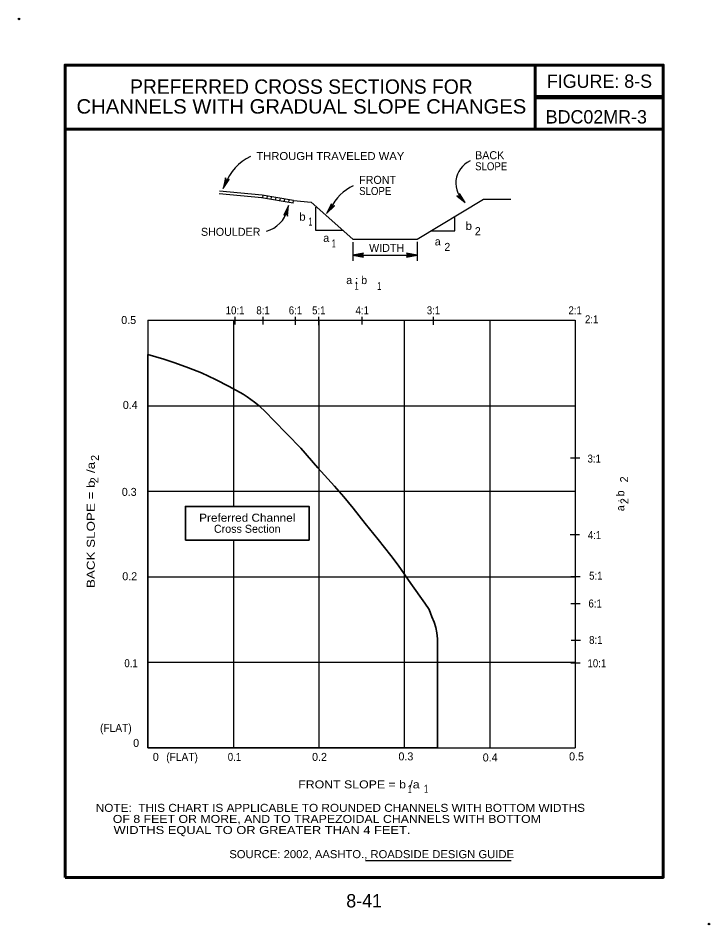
# Model space of a CAD drawing. Extents: x 12.266 to 12.941, y 5.964 to 6.848.
import ezdxf
from ezdxf.enums import TextEntityAlignment as Align

# ---------------------------------------------------------------- set-up
doc = ezdxf.new("R2010")
doc.units = 0
doc.header["$LTSCALE"] = 0.0031
doc.header["$PDMODE"] = 32
doc.header["$PDSIZE"] = 0.00155
doc.layers.add('1', color=7, linetype='Continuous', lineweight=25)
doc.layers.add('24', color=7, linetype='Continuous', lineweight=25)

msp = doc.modelspace()

# ---------------------------------------------------------------- linework, layer by layer
at = {"layer": '1', "lineweight": 60}
for p, q in [((12.769958, 6.73995), (12.769958, 6.802475)), ((12.895008, 6.771217), (12.769958, 6.771217)), ((12.895008, 6.771208), (12.769958, 6.771208)), ((12.895008, 6.73995), (12.311442, 6.73995))]:
    msp.add_line(p, q, dxfattribs=at)
at = {"layer": '1', "lineweight": 90}
msp.add_line((12.770025, 6.771233), (12.895008, 6.771233), dxfattribs=at)
at = {"layer": '1'}
for p, q in [((12.503358, 6.673242), (12.461833, 6.676883)), ((12.504283, 6.673117), (12.504742, 6.675692)), ((12.508517, 6.672367), (12.508975, 6.674942)), ((12.533908, 6.667842), (12.503133, 6.673275)), ((12.512542, 6.67165), (12.513, 6.674225)), ((12.516842, 6.670875), (12.5173, 6.67345)), ((12.521108, 6.670117), (12.521567, 6.672692)), ((12.525242, 6.669392), (12.5257, 6.671958)), ((12.529633, 6.668608), (12.530092, 6.671183)), ((12.533908, 6.667842), (12.534375, 6.670417)), ((12.534375, 6.670417), (12.5517, 6.668908)), ((12.592292, 6.632867), (12.5517, 6.668908)), ((12.654817, 6.632867), (12.719567, 6.671783)), ((12.719567, 6.671783), (12.746233, 6.671783)), ((12.556067, 6.64125), (12.556067, 6.664133)), ((12.691667, 6.640917), (12.691667, 6.654792)), ((12.582117, 6.64125), (12.556067, 6.64125)), ((12.668217, 6.640917), (12.691667, 6.640917)), ((12.592292, 6.632867), (12.654817, 6.632867)), ((12.592292, 6.6299), (12.592292, 6.611658)), ((12.654817, 6.630217), (12.654817, 6.611658)), ((12.592292, 6.617233), (12.654817, 6.617233)), ((12.392242, 6.553717), (12.392242, 6.136883)), ((12.475608, 6.553717), (12.475608, 6.37225)), ((12.4773, 6.549542), (12.4773, 6.557042)), ((12.504592, 6.549725), (12.504592, 6.557042)), ((12.536217, 6.549225), (12.536217, 6.557042)), ((12.558975, 6.548908), (12.558975, 6.557042)), ((12.558975, 6.553717), (12.558975, 6.136883)), ((12.601367, 6.549542), (12.601367, 6.557042)), ((12.642342, 6.553717), (12.642342, 6.136883)), ((12.670892, 6.549225), (12.670892, 6.557042)), ((12.725708, 6.553717), (12.725708, 6.136883)), ((12.392242, 6.47035), (12.809075, 6.47035)), ((12.804683, 6.419567), (12.813775, 6.419567)), ((12.392242, 6.386983), (12.809075, 6.386983)), ((12.475608, 6.339442), (12.475608, 6.136883)), ((12.804375, 6.344725), (12.813458, 6.344725)), ((12.392242, 6.303617), (12.809075, 6.303617)), ((12.805, 6.303875), (12.814083, 6.303875)), ((12.805, 6.27775), (12.814083, 6.27775)), ((12.805317, 6.241892), (12.8144, 6.241892)), ((12.392242, 6.22025), (12.809075, 6.22025)), ((12.805, 6.21975), (12.814083, 6.21975)), ((12.392242, 6.136883), (12.809075, 6.136883)), ((12.604633, 6.027142), (12.746742, 6.027142))]:
    msp.add_line(p, q, dxfattribs=at)
at = {"layer": '1', "lineweight": 60}
msp.add_lwpolyline([(12.311442, 6.010492), (12.895008, 6.010492), (12.895008, 6.802475), (12.311442, 6.802475)], close=True, dxfattribs=at)
at = {"layer": '1'}
for points in [[(12.534375, 6.670417), (12.503592, 6.67585), (12.462058, 6.679483)], [(12.392242, 6.553717), (12.809075, 6.553717), (12.809075, 6.136883)]]:
    msp.add_lwpolyline(points, dxfattribs=at)
at = {"layer": '1', "lineweight": 35}
for points in [[(12.67475, 6.136883), (12.392242, 6.136883), (12.392242, 6.520367), (12.407892, 6.515742), (12.418675, 6.51235), (12.431858, 6.507475), (12.444483, 6.502492), (12.458083, 6.495908), (12.4716, 6.48915), (12.48515, 6.481592), (12.489, 6.4792), (12.496258, 6.473808), (12.500725, 6.470208), (12.507225, 6.464208), (12.514708, 6.45625), (12.541375, 6.428908), (12.557983, 6.409867), (12.57435, 6.392008), (12.583442, 6.381567), (12.592625, 6.370475), (12.604267, 6.355458), (12.616842, 6.340042), (12.629108, 6.324375), (12.636367, 6.314967), (12.648883, 6.297033), (12.66235, 6.278025), (12.666592, 6.271617), (12.669358, 6.264442), (12.671517, 6.259358), (12.673275, 6.254067), (12.674208, 6.248967), (12.67475, 6.243075)], [(12.67475, 6.136883), (12.392242, 6.136883), (12.392242, 6.520367), (12.407892, 6.515742), (12.418675, 6.51235), (12.431858, 6.507475), (12.444483, 6.502492), (12.458083, 6.495908), (12.4716, 6.48915), (12.48515, 6.481592), (12.489, 6.4792), (12.496258, 6.473808), (12.500725, 6.470208), (12.507225, 6.464208), (12.514708, 6.45625), (12.541375, 6.428908), (12.557983, 6.409867), (12.57435, 6.392008), (12.583442, 6.381567), (12.592625, 6.370475), (12.604267, 6.355458), (12.616842, 6.340042), (12.629108, 6.324375), (12.636367, 6.314967), (12.648883, 6.297033), (12.66235, 6.278025), (12.666592, 6.271617), (12.669358, 6.264442), (12.671517, 6.259358), (12.673275, 6.254067), (12.674208, 6.248967), (12.67475, 6.243075)], [(12.4289, 6.339442), (12.549483, 6.339442), (12.549483, 6.37225), (12.4289, 6.37225)]]:
    msp.add_lwpolyline(points, close=True, dxfattribs=at)
at = {"layer": '1'}
msp.add_lwpolyline([(12.4289, 6.339442), (12.549483, 6.339442), (12.549483, 6.37225), (12.4289, 6.37225)], close=True, dxfattribs=at)
for centre, radius, start, end in [((12.516913, 6.666006), 0.053529, 117.42279, 157.44218), ((12.716749, 6.68731), 0.0241, 115.10644, 231.57602), ((12.613717, 6.641686), 0.048143, 115.94415, 153.35158), ((12.499579, 6.669201), 0.029882, 286.38176, 344.91872)]:
    msp.add_arc(centre, radius, start, end, dxfattribs=at)
for p in [(12.266417, 6.84755), (12.93975, 5.96505)]:
    msp.add_point(p, dxfattribs=at)
at = {"layer": '24'}
for points in [[(12.465825, 6.68225), (12.471508, 6.691142), (12.468858, 6.689558), (12.468117, 6.692492), (12.465825, 6.68225), (12.466067, 6.682892), (12.471267, 6.690925), (12.468758, 6.689383), (12.468092, 6.69205), (12.466183, 6.68325), (12.466358, 6.68355), (12.470775, 6.69045), (12.468742, 6.689333), (12.46815, 6.691592), (12.466425, 6.6837), (12.466508, 6.684033), (12.470383, 6.690058), (12.468733, 6.689258), (12.4681, 6.691033), (12.466892, 6.684958), (12.467117, 6.6855), (12.469942, 6.689675), (12.468717, 6.689142), (12.468158, 6.690492), (12.467208, 6.685583), (12.46745, 6.686083), (12.469458, 6.689267), (12.468517, 6.688883), (12.468158, 6.689867), (12.467617, 6.686567), (12.467867, 6.687025), (12.469108, 6.688925), (12.468508, 6.688775), (12.468225, 6.68955), (12.467917, 6.6873), (12.4688, 6.688508), (12.46835, 6.688467), (12.468225, 6.689208), (12.468008, 6.687658), (12.4686, 6.688442), (12.46815, 6.6882), (12.468158, 6.688692), (12.46825, 6.688158), (12.468392, 6.688358)], [(12.701775, 6.668425), (12.696225, 6.677408), (12.696517, 6.674333), (12.693542, 6.674958), (12.701775, 6.668425), (12.7013, 6.668933), (12.696325, 6.677108), (12.696625, 6.674183), (12.693933, 6.674733), (12.701025, 6.669192), (12.700833, 6.669483), (12.696542, 6.676458), (12.696658, 6.674142), (12.694367, 6.674592), (12.700725, 6.669608), (12.700458, 6.669825), (12.696725, 6.675942), (12.696725, 6.6741), (12.69485, 6.6743), (12.699792, 6.670575), (12.6994, 6.671017), (12.696883, 6.675367), (12.696825, 6.674033), (12.695358, 6.674125), (12.699367, 6.671125), (12.699033, 6.671558), (12.697033, 6.67475), (12.696975, 6.673742), (12.695925, 6.673842), (12.698667, 6.671917), (12.698358, 6.67235), (12.697192, 6.674292), (12.697058, 6.673692), (12.696242, 6.673775), (12.698142, 6.672508), (12.697433, 6.673825), (12.697275, 6.673408), (12.69655, 6.673617), (12.69785, 6.672758), (12.697392, 6.673625), (12.697433, 6.673117), (12.696983, 6.673333), (12.697508, 6.673192), (12.697392, 6.6734)], [(12.566633, 6.658), (12.574217, 6.665342), (12.571275, 6.664417), (12.571233, 6.667433), (12.566633, 6.658), (12.567025, 6.658575), (12.573942, 6.665183), (12.571142, 6.664267), (12.5711, 6.667017), (12.567217, 6.658892), (12.567458, 6.659142), (12.57335, 6.664842), (12.571108, 6.664225), (12.571058, 6.66655), (12.567558, 6.659275), (12.567717, 6.659583), (12.572883, 6.66455), (12.571092, 6.66415), (12.570883, 6.666033), (12.568308, 6.6604), (12.56865, 6.660875), (12.572367, 6.664275), (12.57105, 6.664042), (12.570817, 6.665492), (12.568758, 6.660925), (12.569108, 6.661358), (12.571792, 6.663992), (12.570792, 6.663833), (12.570675, 6.664883), (12.569375, 6.661783), (12.569725, 6.662183), (12.571383, 6.663733), (12.57075, 6.663733), (12.570667, 6.66455), (12.56985, 6.662433), (12.570975, 6.663408), (12.570525, 6.663467), (12.570575, 6.664217), (12.570017, 6.662758), (12.570767, 6.663392), (12.570283, 6.66325), (12.570392, 6.663733), (12.570367, 6.663192), (12.570542, 6.66335)], [(12.52935, 6.665708), (12.524867, 6.65615), (12.527292, 6.658067), (12.5284, 6.65525), (12.52935, 6.665708), (12.529183, 6.665042), (12.525075, 6.6564), (12.527358, 6.65825), (12.528375, 6.6557), (12.529117, 6.664667), (12.528983, 6.66435), (12.5255, 6.656933), (12.527375, 6.658308), (12.52825, 6.656142), (12.528942, 6.6642), (12.5289, 6.66385), (12.525833, 6.657375), (12.527375, 6.658383), (12.528233, 6.6567), (12.528642, 6.662883), (12.528483, 6.662317), (12.526225, 6.657808), (12.527375, 6.6585), (12.5281, 6.657225), (12.528408, 6.662225), (12.528233, 6.6617), (12.526658, 6.658283), (12.527533, 6.658783), (12.528025, 6.65785), (12.528133, 6.6612), (12.527942, 6.660708), (12.52695, 6.658667), (12.527533, 6.658892), (12.527908, 6.658158), (12.527925, 6.660433), (12.527217, 6.659117), (12.52765, 6.659217), (12.527867, 6.6585), (12.527883, 6.660067), (12.5274, 6.659208), (12.527808, 6.659508), (12.527867, 6.659017), (12.527708, 6.659533), (12.527592, 6.659317)], [(12.592292, 6.617233), (12.602683, 6.6154), (12.6002, 6.617233), (12.602633, 6.619042), (12.592292, 6.617233), (12.592983, 6.61725), (12.602392, 6.615533), (12.600008, 6.617258), (12.602217, 6.6189), (12.59335, 6.617283), (12.5937, 6.617233), (12.601767, 6.6158), (12.599958, 6.617258), (12.601817, 6.618667), (12.593858, 6.617233), (12.5942, 6.617283), (12.60125, 6.616008), (12.599883, 6.617233), (12.601283, 6.6185), (12.595208, 6.617283), (12.595792, 6.617283), (12.600733, 6.616275), (12.599767, 6.6172), (12.6008, 6.618233), (12.5959, 6.617233), (12.59645, 6.6172), (12.600167, 6.616567), (12.59945, 6.617283), (12.600225, 6.618), (12.596967, 6.617233), (12.597492, 6.617183), (12.599717, 6.616758), (12.59935, 6.617258), (12.599958, 6.617808), (12.597758, 6.617233), (12.599217, 6.616883), (12.599, 6.617283), (12.599642, 6.617683), (12.598125, 6.617283), (12.599083, 6.61705), (12.598683, 6.617358), (12.599142, 6.61755), (12.598683, 6.617258), (12.598917, 6.6172)], [(12.654817, 6.617233), (12.644425, 6.619067), (12.646908, 6.617233), (12.644475, 6.615425), (12.654817, 6.617233), (12.654125, 6.617217), (12.644717, 6.618933), (12.6471, 6.617208), (12.644892, 6.615567), (12.65375, 6.617183), (12.653408, 6.617233), (12.645342, 6.618667), (12.64715, 6.617208), (12.645292, 6.6158), (12.65325, 6.617233), (12.6529, 6.617183), (12.645858, 6.618458), (12.647225, 6.617233), (12.645825, 6.615967), (12.6519, 6.617183), (12.651317, 6.617183), (12.646375, 6.618192), (12.647342, 6.617267), (12.6463, 6.616233), (12.651208, 6.617233), (12.65065, 6.617267), (12.646942, 6.6179), (12.647658, 6.617183), (12.646883, 6.616467), (12.650142, 6.617233), (12.649617, 6.617283), (12.647392, 6.617708), (12.647758, 6.617208), (12.64715, 6.616658), (12.64935, 6.617233), (12.647892, 6.617583), (12.648108, 6.617183), (12.647467, 6.616783), (12.648983, 6.617183), (12.648033, 6.617417), (12.648433, 6.617108), (12.647967, 6.616917), (12.648425, 6.617208), (12.648192, 6.617267)]]:
    msp.add_lwpolyline(points, dxfattribs=at)

# ---------------------------------------------------------------- texts
at = {"layer": '1'}
for s, height, p in [('FIGURE: 8-S', 0.01303, (12.8328, 6.780333)), ('PREFERRED CROSS SECTIONS FOR', 0.01406, (12.542004, 6.77455)), ('BDC02MR-3', 0.01303, (12.829721, 6.745583)), ('Cross Section', 0.007808, (12.489192, 6.346542)), ('8-41', 0.01303, (12.603225, 5.981258))]:
    msp.add_text(s, height=height, dxfattribs=at).set_placement(p, align=Align.CENTER)
for s, height, width, p in [('CHANNELS WITH GRADUAL SLOPE CHANGES', 0.01406, 1.05, (12.542, 6.75525)), ('10:1', 0.007808, 0.9, (12.4773, 6.559525)), ('8:1', 0.007808, 0.9, (12.504592, 6.559525)), ('6:1', 0.007808, 0.9, (12.536217, 6.559525)), ('5:1', 0.007808, 0.9, (12.558975, 6.559525)), ('4:1', 0.007808, 0.9, (12.601367, 6.559525)), ('3:1', 0.007808, 0.9, (12.670892, 6.559525)), ('2:1', 0.007808, 0.9, (12.809075, 6.559525)), ('Preferred Channel', 0.007808, 1.1, (12.489187, 6.35735))]:
    msp.add_text(s, height=height, dxfattribs=dict(at, width=width)).set_placement(p, align=Align.CENTER)
for s, width, p in [('THROUGH TRAVELED WAY', 1.05, (12.498033, 6.709958)), ('SLOPE', 0.9, (12.711492, 6.699975)), ('SLOPE', 0.9, (12.598358, 6.675908)), ('b', 1.1, (12.5398, 6.650858)), ('1', 0.6, (12.548858, 6.646058)), ('b', 1.1, (12.702108, 6.641867)), ('1', 0.6, (12.571642, 6.624792)), ('1', 0.6, (12.593867, 6.583517)), ('1', 0.6, (12.616025, 6.583292)), ('2:1', 0.9, (12.818692, 6.550808)), ('3:1', 0.9, (12.821167, 6.414967)), ('4:1', 0.9, (12.821467, 6.340433)), ('5:1', 0.9, (12.822717, 6.300825)), ('6:1', 0.9, (12.822083, 6.2737)), ('8:1', 0.9, (12.822717, 6.238142)), ('0.1', 0.9, (12.369283, 6.215475)), ('10:1', 0.9, (12.82115, 6.215383)), ('(FLAT)', 0.95, (12.345575, 6.152392)), ('(FLAT)', 0.95, (12.410158, 6.124125)), ('0.1', 0.9, (12.470175, 6.124125)), ('FRONT SLOPE = b /a', 1.15, (12.538942, 6.097333)), ('1', 0.6, (12.645767, 6.092742)), ('1', 0.6, (12.661667, 6.093025)), ('NOTE:  THIS CHART IS APPLICABLE TO ROUNDED CHANNELS WITH BOTTOM WIDTHS', 1.1, (12.341367, 6.07445)), ('     OF 8 FEET OR MORE, AND TO TRAPEZOIDAL CHANNELS WITH BOTTOM', 1.15, (12.341367, 6.063642)), ('     WIDTHS EQUAL TO OR GREATER THAN 4 FEET.', 1.2, (12.341367, 6.052833)), ('SOURCE: 2002, AASHTO., ROADSIDE DESIGN GUIDE', 1.05, (12.471683, 6.029325))]:
    msp.add_text(s, height=0.007808, dxfattribs=dict(at, width=width)).set_placement(p)
for s, p in [('BACK', (12.711492, 6.710783)), ('FRONT', (12.598358, 6.686717)), ('SHOULDER', (12.444008, 6.636083)), ('2', (12.711208, 6.636708)), ('a', (12.56335, 6.630125)), ('a', (12.672092, 6.626733)), ('WIDTH', (12.608058, 6.620392)), ('2', (12.681442, 6.621367)), ('a : b', (12.585775, 6.589042)), ('0.5', (12.366258, 6.550058)), ('0.4', (12.367775, 6.4673)), ('0.3', (12.366775, 6.382517)), ('0.2', (12.367258, 6.30025)), ('0', (12.377858, 6.13775)), ('0', (12.397033, 6.124125)), ('0.2', (12.552417, 6.124117)), ('0.3', (12.636683, 6.124625)), ('0.4', (12.718917, 6.123617)), ('0.5', (12.803167, 6.124608))]:
    msp.add_text(s, height=0.007808, dxfattribs=at).set_placement(p)
for s, p in [('2', (12.344492, 6.416667)), ('2', (12.860767, 6.395683)), ('2', (12.34395, 6.39495)), ('a : b', (12.857092, 6.36755)), ('2', (12.861058, 6.374517))]:
    msp.add_text(s, height=0.007808, rotation=90, dxfattribs=at).set_placement(p)
at = {"layer": '1', "width": 1.25}
msp.add_text('BACK SLOPE = b  /a', height=0.007808, rotation=90, dxfattribs=at).set_placement((12.34045, 6.292725))

doc.saveas('drawing.dxf')
